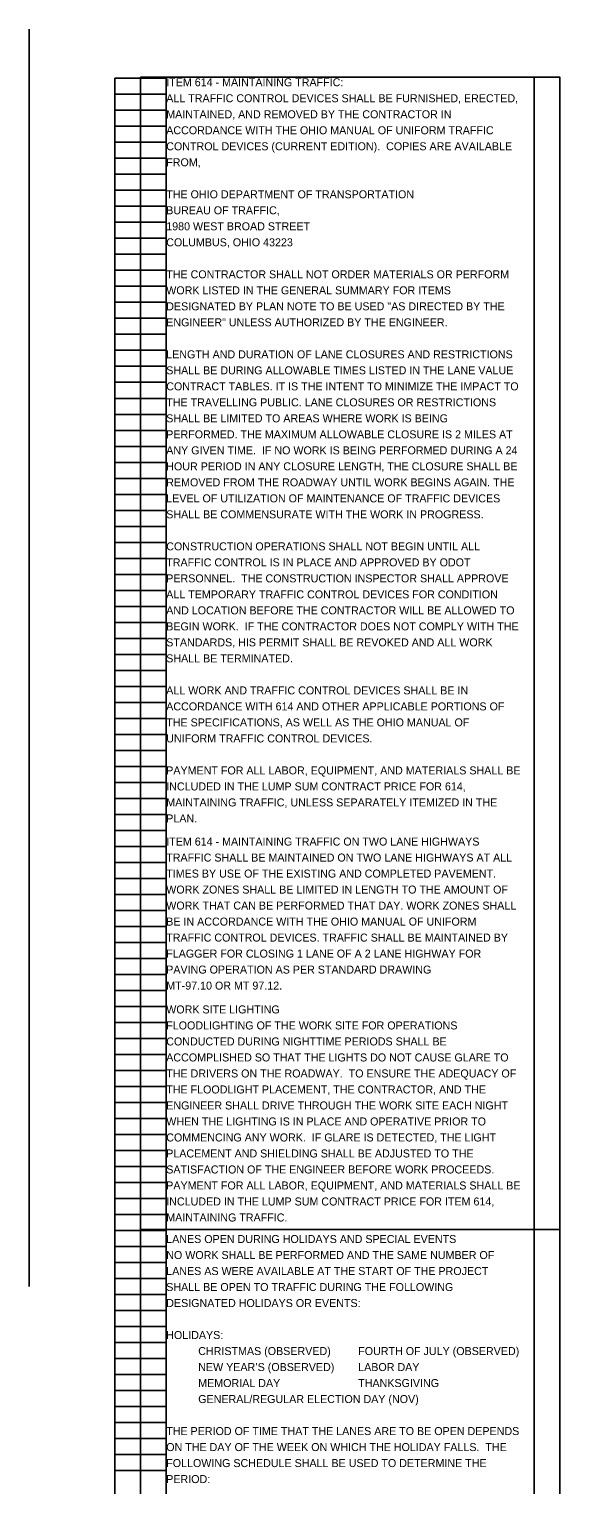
# Model space of a CAD drawing. Extents: x 0 to 19, y -301 to 22.
# Drawn here: x 0 to 9.29, y -3.47 to 22 of the extents above; entities that cross this region are included whole.
import ezdxf

# ---------------------------------------------------------------- set-up
doc = ezdxf.new("R2010")
doc.units = 0
doc.layers.add('SC_Scratch1', color=7, linetype='Continuous')
doc.layers.add('SH_Text', color=7, linetype='Continuous')

msp = doc.modelspace()

# ---------------------------------------------------------------- linework, layer by layer
at = {"layer": 'SC_Scratch1'}
for p, q in [((0, 22), (0, 0)), ((1.5, 21.14), (2.4, 21.14)), ((1.5, 0.98), (1.5, 21.14)), ((2.4, 0.98), (2.4, 21.14)), ((8.84, 0.98), (8.84, 21.14)), ((1.5, 20.86), (2.4, 20.86)), ((1.5, 20.58), (2.4, 20.58)), ((1.5, 20.3), (2.4, 20.3)), ((1.5, 20.02), (2.4, 20.02)), ((1.5, 19.74), (2.4, 19.74)), ((1.5, 19.46), (2.4, 19.46)), ((1.5, 19.18), (2.4, 19.18)), ((1.5, 18.9), (2.4, 18.9)), ((1.5, 18.62), (2.4, 18.62)), ((1.5, 18.34), (2.4, 18.34)), ((1.5, 18.06), (2.4, 18.06)), ((1.5, 17.78), (2.4, 17.78)), ((1.5, 17.5), (2.4, 17.5)), ((1.5, 17.22), (2.4, 17.22)), ((1.5, 16.94), (2.4, 16.94)), ((1.5, 16.66), (2.4, 16.66)), ((1.5, 16.38), (2.4, 16.38)), ((1.5, 16.1), (2.4, 16.1)), ((1.5, 15.82), (2.4, 15.82)), ((1.5, 15.54), (2.4, 15.54)), ((1.5, 15.26), (2.4, 15.26)), ((1.5, 14.98), (2.4, 14.98)), ((1.5, 14.7), (2.4, 14.7)), ((1.5, 14.42), (2.4, 14.42)), ((1.5, 14.14), (2.4, 14.14)), ((1.5, 13.86), (2.4, 13.86)), ((1.5, 13.58), (2.4, 13.58)), ((1.5, 13.3), (2.4, 13.3)), ((1.5, 13.02), (2.4, 13.02)), ((1.5, 12.74), (2.4, 12.74)), ((1.5, 12.46), (2.4, 12.46)), ((1.5, 12.18), (2.4, 12.18)), ((1.5, 11.9), (2.4, 11.9)), ((1.5, 11.62), (2.4, 11.62)), ((1.5, 11.34), (2.4, 11.34)), ((1.5, 11.06), (2.4, 11.06)), ((1.5, 10.78), (2.4, 10.78)), ((1.5, 10.5), (2.4, 10.5)), ((1.5, 10.22), (2.4, 10.22)), ((1.5, 9.94), (2.4, 9.94)), ((1.5, 9.66), (2.4, 9.66)), ((1.5, 9.38), (2.4, 9.38)), ((1.5, 9.1), (2.4, 9.1)), ((1.5, 8.82), (2.4, 8.82)), ((1.5, 8.54), (2.4, 8.54)), ((1.5, 8.26), (2.4, 8.26)), ((1.5, 7.98), (2.4, 7.98)), ((1.5, 7.7), (2.4, 7.7)), ((1.5, 7.42), (2.4, 7.42)), ((1.5, 7.14), (2.4, 7.14)), ((1.5, 6.86), (2.4, 6.86)), ((1.5, 6.58), (2.4, 6.58)), ((1.5, 6.3), (2.4, 6.3)), ((1.5, 6.02), (2.4, 6.02)), ((1.5, 5.74), (2.4, 5.74)), ((1.5, 5.46), (2.4, 5.46)), ((1.5, 5.18), (2.4, 5.18)), ((1.5, 4.9), (2.4, 4.9)), ((1.5, 4.62), (2.4, 4.62)), ((1.5, 4.34), (2.4, 4.34)), ((1.5, 4.06), (2.4, 4.06)), ((1.5, 3.78), (2.4, 3.78)), ((1.5, 3.5), (2.4, 3.5)), ((1.5, 3.22), (2.4, 3.22)), ((1.5, 2.94), (2.4, 2.94)), ((1.5, 2.66), (2.4, 2.66)), ((1.5, 2.38), (2.4, 2.38)), ((1.5, 2.1), (2.4, 2.1)), ((1.5, 1.82), (2.4, 1.82)), ((1.5, 1.54), (2.4, 1.54)), ((1.5, 1.26), (2.4, 1.26)), ((1.5, 0.98), (2.4, 0.98)), ((1.5, 0.98), (2.4, 0.98)), ((1.5, -19.18), (1.5, 0.98)), ((2.4, -19.18), (2.4, 0.98)), ((8.84, -19.18), (8.84, 0.98)), ((1.5, 0.7), (2.4, 0.7)), ((1.5, 0.42), (2.4, 0.42)), ((1.5, 0.14), (2.4, 0.14)), ((1.5, -0.14), (2.4, -0.14)), ((1.5, -0.42), (2.4, -0.42)), ((1.5, -0.7), (2.4, -0.7)), ((1.5, -0.98), (2.4, -0.98)), ((1.5, -1.26), (2.4, -1.26)), ((1.5, -1.54), (2.4, -1.54)), ((1.5, -1.82), (2.4, -1.82)), ((1.5, -2.1), (2.4, -2.1)), ((1.5, -2.38), (2.4, -2.38)), ((1.5, -2.66), (2.4, -2.66)), ((1.5, -2.94), (2.4, -2.94)), ((1.5, -3.22), (2.4, -3.22))]:
    msp.add_line(p, q, dxfattribs=at)
for points in [[(1.95, 21.157), (9.29, 21.157), (9.29, 0.997), (1.95, 0.997)], [(1.95, 0.997), (9.29, 0.997), (9.29, -19.163), (1.95, -19.163)]]:
    msp.add_lwpolyline(points, close=True, dxfattribs=at)

# ---------------------------------------------------------------- texts
at = {"layer": 'SH_Text'}
for s, p in [('ITEM 614 - MAINTAINING TRAFFIC:', (2.4, 21)), ('ALL TRAFFIC CONTROL DEVICES SHALL BE FURNISHED, ERECTED, ', (2.4, 20.72)), ('MAINTAINED, AND REMOVED BY THE CONTRACTOR IN ', (2.4, 20.44)), ('ACCORDANCE WITH THE OHIO MANUAL OF UNIFORM TRAFFIC ', (2.4, 20.16)), ('CONTROL DEVICES (CURRENT EDITION).  COPIES ARE AVAILABLE ', (2.4, 19.88)), ('FROM,', (2.4, 19.6)), ('THE OHIO DEPARTMENT OF TRANSPORTATION', (2.4, 19.04)), ('BUREAU OF TRAFFIC,', (2.4, 18.76)), ('1980 WEST BROAD STREET', (2.4, 18.48)), ('COLUMBUS, OHIO 43223', (2.4, 18.2)), ('THE CONTRACTOR SHALL NOT ORDER MATERIALS OR PERFORM ', (2.4, 17.64)), ('WORK LISTED IN THE GENERAL SUMMARY FOR ITEMS ', (2.4, 17.36)), ('DESIGNATED BY PLAN NOTE TO BE USED "AS DIRECTED BY THE ', (2.4, 17.08)), ('ENGINEER" UNLESS AUTHORIZED BY THE ENGINEER.', (2.4, 16.8)), ('LENGTH AND DURATION OF LANE CLOSURES AND RESTRICTIONS ', (2.4, 16.24)), ('SHALL BE DURING ALLOWABLE TIMES LISTED IN THE LANE VALUE ', (2.4, 15.96)), ('CONTRACT TABLES. IT IS THE INTENT TO MINIMIZE THE IMPACT TO ', (2.4, 15.68)), ('THE TRAVELLING PUBLIC. LANE CLOSURES OR RESTRICTIONS ', (2.4, 15.4)), ('SHALL BE LIMITED TO AREAS WHERE WORK IS BEING ', (2.4, 15.12)), ('PERFORMED. THE MAXIMUM ALLOWABLE CLOSURE IS 2 MILES AT ', (2.4, 14.84)), ('ANY GIVEN TIME.  IF NO WORK IS BEING PERFORMED DURING A 24 ', (2.4, 14.56)), ('HOUR PERIOD IN ANY CLOSURE LENGTH, THE CLOSURE SHALL BE ', (2.4, 14.28)), ('REMOVED FROM THE ROADWAY UNTIL WORK BEGINS AGAIN. THE ', (2.4, 14)), ('LEVEL OF UTILIZATION OF MAINTENANCE OF TRAFFIC DEVICES ', (2.4, 13.72)), ('SHALL BE COMMENSURATE WITH THE WORK IN PROGRESS.', (2.4, 13.44)), ('CONSTRUCTION OPERATIONS SHALL NOT BEGIN UNTIL ALL ', (2.4, 12.88)), ('TRAFFIC CONTROL IS IN PLACE AND APPROVED BY ODOT ', (2.4, 12.6)), ('PERSONNEL.  THE CONSTRUCTION INSPECTOR SHALL APPROVE ', (2.4, 12.32)), ('ALL TEMPORARY TRAFFIC CONTROL DEVICES FOR CONDITION ', (2.4, 12.04)), ('AND LOCATION BEFORE THE CONTRACTOR WILL BE ALLOWED TO ', (2.4, 11.76)), ('BEGIN WORK.  IF THE CONTRACTOR DOES NOT COMPLY WITH THE ', (2.4, 11.48)), ('STANDARDS, HIS PERMIT SHALL BE REVOKED AND ALL WORK ', (2.4, 11.2)), ('SHALL BE TERMINATED.', (2.4, 10.92)), ('ALL WORK AND TRAFFIC CONTROL DEVICES SHALL BE IN ', (2.4, 10.36)), ('ACCORDANCE WITH 614 AND OTHER APPLICABLE PORTIONS OF ', (2.4, 10.08)), ('THE SPECIFICATIONS, AS WELL AS THE OHIO MANUAL OF ', (2.4, 9.8)), ('UNIFORM TRAFFIC CONTROL DEVICES.  ', (2.4, 9.52)), ('PAYMENT FOR ALL LABOR, EQUIPMENT, AND MATERIALS SHALL BE ', (2.4, 8.96)), ('INCLUDED IN THE LUMP SUM CONTRACT PRICE FOR 614, ', (2.4, 8.68)), ('MAINTAINING TRAFFIC, UNLESS SEPARATELY ITEMIZED IN THE ', (2.4, 8.4)), ('PLAN.', (2.4, 8.12)), ('ITEM 614 - MAINTAINING TRAFFIC ON TWO LANE HIGHWAYS', (2.4, 7.715)), ('TRAFFIC SHALL BE MAINTAINED ON TWO LANE HIGHWAYS AT ALL ', (2.4, 7.435)), ('TIMES BY USE OF THE EXISTING AND COMPLETED PAVEMENT.  ', (2.4, 7.155)), ('WORK ZONES SHALL BE LIMITED IN LENGTH TO THE AMOUNT OF ', (2.4, 6.875)), ('WORK THAT CAN BE PERFORMED THAT DAY. WORK ZONES SHALL ', (2.4, 6.595)), ('BE IN ACCORDANCE WITH THE OHIO MANUAL OF UNIFORM ', (2.4, 6.315)), ('TRAFFIC CONTROL DEVICES. TRAFFIC SHALL BE MAINTAINED BY ', (2.4, 6.035)), ('FLAGGER FOR CLOSING 1 LANE OF A 2 LANE HIGHWAY FOR ', (2.4, 5.755)), ('PAVING OPERATION AS PER STANDARD DRAWING', (2.4, 5.475)), ('MT-97.10 OR MT 97.12.', (2.4, 5.195)), ('WORK SITE LIGHTING', (2.4, 4.778)), ('FLOODLIGHTING OF THE WORK SITE FOR OPERATIONS ', (2.4, 4.498)), ('CONDUCTED DURING NIGHTTIME PERIODS SHALL BE ', (2.4, 4.218)), ('ACCOMPLISHED SO THAT THE LIGHTS DO NOT CAUSE GLARE TO ', (2.4, 3.938)), ('THE DRIVERS ON THE ROADWAY.  TO ENSURE THE ADEQUACY OF ', (2.4, 3.658)), ('THE FLOODLIGHT PLACEMENT, THE CONTRACTOR, AND THE ', (2.4, 3.378)), ('ENGINEER SHALL DRIVE THROUGH THE WORK SITE EACH NIGHT ', (2.4, 3.098)), ('WHEN THE LIGHTING IS IN PLACE AND OPERATIVE PRIOR TO ', (2.4, 2.818)), ('COMMENCING ANY WORK.  IF GLARE IS DETECTED, THE LIGHT ', (2.4, 2.538)), ('PLACEMENT AND SHIELDING SHALL BE ADJUSTED TO THE ', (2.4, 2.258)), ('SATISFACTION OF THE ENGINEER BEFORE WORK PROCEEDS.  ', (2.4, 1.978)), ('PAYMENT FOR ALL LABOR, EQUIPMENT, AND MATERIALS SHALL BE ', (2.4, 1.698)), ('INCLUDED IN THE LUMP SUM CONTRACT PRICE FOR ITEM 614, ', (2.4, 1.418)), ('MAINTAINING TRAFFIC.', (2.4, 1.138)), ('LANES OPEN DURING HOLIDAYS AND SPECIAL EVENTS', (2.4, 0.761)), ('NO WORK SHALL BE PERFORMED AND THE SAME NUMBER OF ', (2.4, 0.481)), ('LANES AS WERE AVAILABLE AT THE START OF THE PROJECT ', (2.4, 0.201)), ('SHALL BE OPEN TO TRAFFIC DURING THE FOLLOWING ', (2.4, -0.079)), ('DESIGNATED HOLIDAYS OR EVENTS:', (2.4, -0.359)), ('HOLIDAYS:', (2.4, -0.919)), ('CHRISTMAS (OBSERVED)', (2.96, -1.199)), ('FOURTH OF JULY (OBSERVED)', (5.76, -1.199)), ('NEW YEAR’S (OBSERVED)', (2.96, -1.479)), ('LABOR DAY', (5.76, -1.479)), ('MEMORIAL DAY          ', (2.96, -1.759)), ('THANKSGIVING', (5.76, -1.759)), ('GENERAL/REGULAR ELECTION DAY (NOV)', (2.96, -2.039)), ('THE PERIOD OF TIME THAT THE LANES ARE TO BE OPEN DEPENDS ', (2.4, -2.599)), ('ON THE DAY OF THE WEEK ON WHICH THE HOLIDAY FALLS.  THE ', (2.4, -2.879)), ('FOLLOWING SCHEDULE SHALL BE USED TO DETERMINE THE ', (2.4, -3.159)), ('PERIOD:', (2.4, -3.439))]:
    msp.add_text(s, height=0.14, dxfattribs=at).set_placement(p)

doc.saveas('drawing.dxf')
